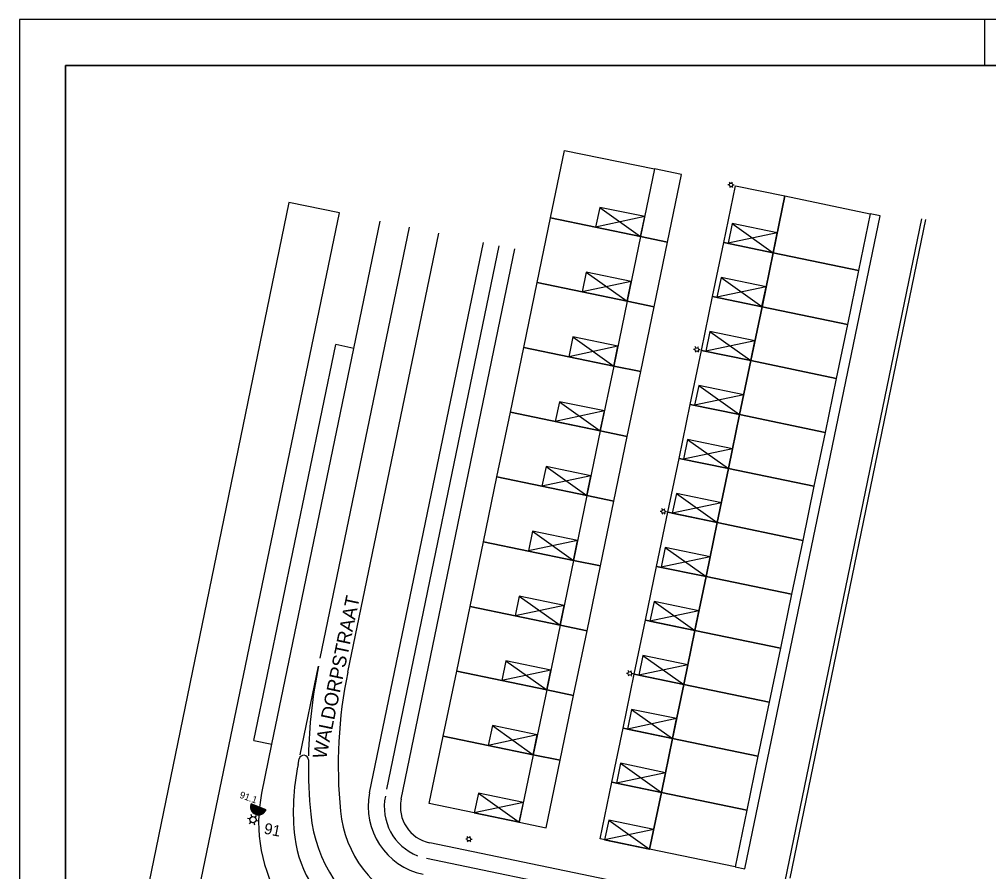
# Model space of a CAD drawing. Extents: x 81065 to 81486, y 452384 to 452681.
# Drawn here: x 81065.2 to 81170.8, y 452587.8 to 452680.5 of the extents above; entities that cross this region are included whole.
import ezdxf

# ---------------------------------------------------------------- set-up
doc = ezdxf.new("R2010")
doc.units = 0
for name, color, linetype in [('B-BH-AL-TOPOGRAFIE_STRAATNAAM-S', 7, 'Continuous'), ('B-BH-IE-MEUBILAIR_WEGMEUBILAIR_LICHTMAST-S', 7, 'Continuous'), ('B-BH-OG-TOPOGRAFIE_BEBOUWING-GV', 7, 'Continuous'), ('B-BH-OG-TOPOGRAFIE_BEBOUWING_PANDSCHEIDING-GV', 7, 'Continuous'), ('B-BH-VH-KANTOPSLUITING-GV', 7, 'Continuous'), ('B-WE-VW-MARKERING_LANGS_STREEP_13_010-G', 7, 'Continuous'), ('B-WE-VW-MARKERING_LANGS_STREEP_30270_010-G', 7, 'Continuous'), ('B-WE-VW-MARKERING_LANGS_STREEP_DOORGETROKKEN_010-G', 7, 'Continuous'), ('N-WE-VW-VRI_ARMATUUR-S', 7, 'Continuous'), ('N-WE-VW-VRI_ARMATUUR-T18', 7, 'Continuous'), ('N-WE-VW-VRI_MAST-S', 7, 'Continuous'), ('N-WE-VW-VRI_RICHTINGNUMMER-T25', 7, 'Continuous'), ('X-XX-AL-TEKENBLAD_KADER-G', 7, 'Continuous'), ('X-XX-AL-TEKENBLAD_KADER_AFSNIJMARKERING-G', 7, 'Continuous'), ('X-XX-AL-TEKENBLAD_KADER_VOUWMERK-G', 7, 'Continuous'), ('X-XX-AL-TEKENBLAD_VIEWPORT-G', 7, 'Continuous')]:
    doc.layers.add(name, color=color, linetype=linetype)

msp = doc.modelspace()

# ---------------------------------------------------------------- linework, layer by layer
at = {"layer": 'B-BH-IE-MEUBILAIR_WEGMEUBILAIR_LICHTMAST-S'}
for p, q in [((81142.5, 452662.52), (81142.35, 452662.52)), ((81142.6, 452662.7), (81142.52, 452662.83)), ((81142.8, 452662.7), (81142.87, 452662.83)), ((81142.9, 452662.52), (81143.05, 452662.52)), ((81142.6, 452662.35), (81142.52, 452662.22)), ((81142.8, 452662.35), (81142.87, 452662.22)), ((81138.78, 452644.6), (81138.63, 452644.6)), ((81138.88, 452644.78), (81138.81, 452644.91)), ((81139.08, 452644.78), (81139.16, 452644.91)), ((81139.18, 452644.6), (81139.33, 452644.6)), ((81138.88, 452644.43), (81138.81, 452644.3)), ((81139.08, 452644.43), (81139.16, 452644.3)), ((81135.13, 452626.98), (81134.98, 452626.98)), ((81135.23, 452627.15), (81135.16, 452627.28)), ((81135.23, 452626.8), (81135.16, 452626.67)), ((81135.43, 452627.15), (81135.51, 452627.28)), ((81135.43, 452626.8), (81135.51, 452626.67)), ((81135.53, 452626.98), (81135.68, 452626.98)), ((81131.58, 452609.52), (81131.51, 452609.65)), ((81131.78, 452609.52), (81131.86, 452609.65)), ((81131.48, 452609.35), (81131.33, 452609.35)), ((81131.58, 452609.18), (81131.51, 452609.05)), ((81131.78, 452609.18), (81131.86, 452609.05)), ((81131.88, 452609.35), (81132.03, 452609.35)), ((81113.96, 452591.31), (81113.81, 452591.31)), ((81114.06, 452591.48), (81113.98, 452591.61)), ((81114.06, 452591.14), (81113.98, 452591.01)), ((81114.26, 452591.48), (81114.33, 452591.61)), ((81114.26, 452591.14), (81114.33, 452591.01)), ((81114.36, 452591.31), (81114.51, 452591.31))]:
    msp.add_line(p, q, dxfattribs=at)
for centre in [(81142.7, 452662.52), (81138.98, 452644.6), (81135.33, 452626.98), (81131.68, 452609.35), (81114.16, 452591.31)]:
    msp.add_circle(centre, 0.2, dxfattribs=at)
at = {"layer": 'B-BH-OG-TOPOGRAFIE_BEBOUWING-GV'}
for points in [[(81132.85, 452656.9), (81123.06, 452658.93), (81124.58, 452666.27), (81134.37, 452664.25)], [(81148.57, 452661.31), (81157.87, 452659.38), (81156.6, 452653.21), (81147.29, 452655.14)], [(81132.85, 452656.9), (81131.39, 452649.85), (81121.6, 452651.88), (81123.06, 452658.93)], [(81147.29, 452655.14), (81156.6, 452653.21), (81155.38, 452647.33), (81146.08, 452649.26)], [(81131.39, 452649.85), (81129.93, 452642.8), (81120.14, 452644.83), (81121.6, 452651.88)], [(81146.08, 452649.26), (81155.38, 452647.33), (81154.16, 452641.46), (81144.86, 452643.39)], [(81129.93, 452642.8), (81128.47, 452635.75), (81118.68, 452637.78), (81120.14, 452644.83)], [(81144.86, 452643.39), (81154.16, 452641.46), (81152.94, 452635.58), (81143.64, 452637.51)], [(81128.47, 452635.75), (81127.01, 452628.7), (81117.22, 452630.73), (81118.68, 452637.78)], [(81143.64, 452637.51), (81152.94, 452635.58), (81151.73, 452629.71), (81142.42, 452631.64)], [(81127.01, 452628.7), (81125.55, 452621.65), (81115.76, 452623.68), (81117.22, 452630.73)], [(81142.42, 452631.64), (81151.73, 452629.71), (81150.51, 452623.83), (81141.21, 452625.76)], [(81141.21, 452625.76), (81150.51, 452623.83), (81149.29, 452617.96), (81139.99, 452619.88)], [(81125.55, 452621.65), (81124.09, 452614.6), (81114.3, 452616.63), (81115.76, 452623.68)], [(81139.99, 452619.88), (81149.29, 452617.96), (81148.08, 452612.08), (81138.77, 452614.01)], [(81124.09, 452614.6), (81122.63, 452607.55), (81112.84, 452609.58), (81114.3, 452616.63)], [(81138.77, 452614.01), (81148.08, 452612.08), (81146.86, 452606.21), (81137.56, 452608.13)], [(81122.63, 452607.55), (81121.17, 452600.5), (81111.37, 452602.53), (81112.84, 452609.58)], [(81137.56, 452608.13), (81146.86, 452606.21), (81145.64, 452600.33), (81136.34, 452602.26)], [(81121.17, 452600.5), (81119.65, 452593.16), (81109.85, 452595.18), (81111.37, 452602.53)], [(81136.34, 452602.26), (81145.64, 452600.33), (81144.42, 452594.46), (81135.12, 452596.38)], [(81135.12, 452596.38), (81144.42, 452594.46), (81143.15, 452588.29), (81133.84, 452590.21)]]:
    msp.add_lwpolyline(points, close=True, dxfattribs=at)
at = {"layer": 'B-BH-OG-TOPOGRAFIE_BEBOUWING_PANDSCHEIDING-GV'}
for p, q in [((81128.4, 452660.07), (81132.85, 452656.9)), ((81133.3, 452659.06), (81127.95, 452657.92)), ((81142.84, 452658.31), (81147.29, 452655.14)), ((81147.73, 452657.3), (81142.39, 452656.16)), ((81126.94, 452653.02), (81131.39, 452649.85)), ((81131.84, 452652.01), (81126.49, 452650.87)), ((81141.62, 452652.43), (81146.07, 452649.27)), ((81146.52, 452651.42), (81141.17, 452650.28)), ((81140.4, 452646.56), (81144.85, 452643.39)), ((81125.48, 452645.97), (81129.93, 452642.8)), ((81145.3, 452645.55), (81139.96, 452644.41)), ((81130.38, 452644.96), (81125.03, 452643.82)), ((81139.19, 452640.68), (81143.64, 452637.52)), ((81144.08, 452639.67), (81138.74, 452638.53)), ((81124.02, 452638.92), (81128.47, 452635.75)), ((81128.92, 452637.91), (81123.57, 452636.77)), ((81137.97, 452634.81), (81142.42, 452631.64)), ((81142.86, 452633.79), (81137.52, 452632.65)), ((81122.56, 452631.87), (81127.01, 452628.7)), ((81127.45, 452630.86), (81122.11, 452629.72)), ((81136.75, 452628.93), (81141.2, 452625.77)), ((81141.65, 452627.92), (81136.31, 452626.78)), ((81121.1, 452624.82), (81125.55, 452621.65)), ((81125.99, 452623.81), (81120.65, 452622.67)), ((81135.53, 452623.06), (81139.98, 452619.89)), ((81140.43, 452622.04), (81135.09, 452620.9)), ((81119.64, 452617.77), (81124.09, 452614.6)), ((81134.32, 452617.18), (81138.77, 452614.01)), ((81124.53, 452616.75), (81119.19, 452615.61)), ((81139.21, 452616.17), (81133.87, 452615.03)), ((81118.18, 452610.72), (81122.63, 452607.55)), ((81133.1, 452611.31), (81137.55, 452608.14)), ((81123.07, 452609.7), (81117.73, 452608.56)), ((81138, 452610.29), (81132.65, 452609.15)), ((81131.88, 452605.43), (81136.33, 452602.26)), ((81136.78, 452604.42), (81131.44, 452603.28)), ((81116.72, 452603.67), (81121.17, 452600.5)), ((81121.61, 452602.65), (81116.27, 452601.51)), ((81130.67, 452599.56), (81135.12, 452596.39)), ((81135.56, 452598.54), (81130.22, 452597.4)), ((81115.2, 452596.32), (81119.65, 452593.16)), ((81120.09, 452595.31), (81114.75, 452594.17)), ((81129.39, 452593.39), (81133.84, 452590.22)), ((81134.28, 452592.37), (81128.94, 452591.23))]:
    msp.add_line(p, q, dxfattribs=at)
for points in [[(81127.95, 452657.92), (81132.85, 452656.9), (81133.3, 452659.06), (81128.4, 452660.07)], [(81142.39, 452656.16), (81147.29, 452655.14), (81147.73, 452657.3), (81142.84, 452658.31)], [(81126.49, 452650.87), (81131.39, 452649.85), (81131.84, 452652.01), (81126.94, 452653.02)], [(81141.17, 452650.28), (81146.07, 452649.27), (81146.52, 452651.42), (81141.62, 452652.43)], [(81139.96, 452644.41), (81144.85, 452643.39), (81145.3, 452645.55), (81140.4, 452646.56)], [(81125.03, 452643.82), (81129.93, 452642.8), (81130.38, 452644.96), (81125.48, 452645.97)], [(81138.74, 452638.53), (81143.64, 452637.52), (81144.08, 452639.67), (81139.19, 452640.68)], [(81123.57, 452636.77), (81128.47, 452635.75), (81128.92, 452637.91), (81124.02, 452638.92)], [(81137.52, 452632.65), (81142.42, 452631.64), (81142.86, 452633.79), (81137.97, 452634.81)], [(81122.11, 452629.72), (81127.01, 452628.7), (81127.45, 452630.86), (81122.56, 452631.87)], [(81136.31, 452626.78), (81141.2, 452625.77), (81141.65, 452627.92), (81136.75, 452628.93)], [(81120.65, 452622.67), (81125.55, 452621.65), (81125.99, 452623.81), (81121.1, 452624.82)], [(81135.09, 452620.9), (81139.98, 452619.89), (81140.43, 452622.04), (81135.53, 452623.06)], [(81119.19, 452615.61), (81124.09, 452614.6), (81124.53, 452616.75), (81119.64, 452617.77)], [(81133.87, 452615.03), (81138.77, 452614.01), (81139.21, 452616.17), (81134.32, 452617.18)], [(81117.73, 452608.56), (81122.63, 452607.55), (81123.07, 452609.7), (81118.18, 452610.72)], [(81132.65, 452609.15), (81137.55, 452608.14), (81138, 452610.29), (81133.1, 452611.31)], [(81131.44, 452603.28), (81136.33, 452602.26), (81136.78, 452604.42), (81131.88, 452605.43)], [(81116.27, 452601.51), (81121.17, 452600.5), (81121.61, 452602.65), (81116.72, 452603.67)], [(81130.22, 452597.4), (81135.12, 452596.39), (81135.56, 452598.54), (81130.67, 452599.56)], [(81114.75, 452594.17), (81119.65, 452593.16), (81120.09, 452595.31), (81115.2, 452596.32)], [(81128.94, 452591.23), (81133.84, 452590.22), (81134.28, 452592.37), (81129.39, 452593.39)]]:
    msp.add_lwpolyline(points, close=True, dxfattribs=at)
at = {"layer": 'B-BH-VH-KANTOPSLUITING-GV'}
for p, q in [((81158.95, 452659.16), (81157.87, 452659.38)), ((81101.63, 452644.72), (81104.5, 452658.57)), ((81144.22, 452588.06), (81158.95, 452659.16)), ((81148.61, 452586.73), (81163.49, 452658.84)), ((81149.13, 452587.07), (81163.92, 452658.74)), ((81100.97, 452609.49), (81110.87, 452657.26)), ((81103.35, 452596.34), (81115.75, 452656.26)), ((81106.78, 452595.64), (81119.17, 452655.55)), ((81090.74, 452602.05), (81099.67, 452645.13)), ((81092.7, 452601.64), (81101.63, 452644.72)), ((81101.63, 452644.72), (81099.67, 452645.13)), ((81090.74, 452602.05), (81092.7, 452601.64)), ((81091.6, 452596.31), (81092.7, 452601.64)), ((81191.05, 452574.1), (81109.89, 452590.91)), ((81143.15, 452588.29), (81144.22, 452588.06))]:
    msp.add_line(p, q, dxfattribs=at)
for points in [[(81137.31, 452663.64), (81134.37, 452664.25), (81132.85, 452656.9), (81135.79, 452656.29)], [(81147.29, 452655.14), (81141.91, 452656.25), (81143.18, 452662.42), (81148.57, 452661.31)], [(81135.79, 452656.29), (81132.85, 452656.9), (81131.39, 452649.85), (81134.33, 452649.24)], [(81146.08, 452649.26), (81140.69, 452650.38), (81141.91, 452656.25), (81147.29, 452655.14)], [(81134.33, 452649.24), (81131.39, 452649.85), (81129.93, 452642.8), (81132.87, 452642.19)], [(81144.86, 452643.39), (81139.47, 452644.5), (81140.69, 452650.38), (81146.08, 452649.26)], [(81143.64, 452637.51), (81138.26, 452638.63), (81139.47, 452644.5), (81144.86, 452643.39)], [(81132.87, 452642.19), (81129.93, 452642.8), (81128.47, 452635.75), (81131.41, 452635.14)], [(81142.42, 452631.64), (81137.04, 452632.75), (81138.26, 452638.63), (81143.64, 452637.51)], [(81131.41, 452635.14), (81128.47, 452635.75), (81127.01, 452628.7), (81129.95, 452628.09)], [(81141.21, 452625.76), (81135.82, 452626.88), (81137.04, 452632.75), (81142.42, 452631.64)], [(81129.95, 452628.09), (81127.01, 452628.7), (81125.55, 452621.65), (81128.49, 452621.04)], [(81139.99, 452619.88), (81134.6, 452621), (81135.82, 452626.88), (81141.21, 452625.76)], [(81128.49, 452621.04), (81125.55, 452621.65), (81124.09, 452614.6), (81127.03, 452613.99)], [(81138.77, 452614.01), (81133.39, 452615.13), (81134.6, 452621), (81139.99, 452619.88)], [(81137.56, 452608.13), (81132.17, 452609.25), (81133.39, 452615.13), (81138.77, 452614.01)], [(81127.03, 452613.99), (81124.09, 452614.6), (81122.63, 452607.55), (81125.56, 452606.94)], [(81136.34, 452602.26), (81130.95, 452603.37), (81132.17, 452609.25), (81137.56, 452608.13)], [(81125.56, 452606.94), (81122.63, 452607.55), (81121.17, 452600.5), (81124.1, 452599.89)], [(81135.12, 452596.38), (81129.74, 452597.5), (81130.95, 452603.37), (81136.34, 452602.26)], [(81124.1, 452599.89), (81121.17, 452600.5), (81119.65, 452593.16), (81122.58, 452592.55)], [(81133.84, 452590.21), (81128.46, 452591.33), (81129.74, 452597.5), (81135.12, 452596.38)]]:
    msp.add_lwpolyline(points, close=True, dxfattribs=at)
for points in [[(81100.07, 452659.48), (81094.54, 452660.61), (81078.26, 452581.39)], [(81078.26, 452581.39), (81083.63, 452580.28), (81100.07, 452659.48)]]:
    msp.add_lwpolyline(points, dxfattribs=at)
for centre, radius, start, end in [((81149.93, 452599.34), 50, 168.2893, 185.7359), ((81107.26, 452593.07), 16, 168.2893, 258.3266), ((81110.7, 452594.83), 7.5, 168.3133, 258.2967), ((81110.7, 452594.83), 4, 168.3133, 258.2967), ((81112.61, 452595.59), 12.5, 185.7359, 248.4832)]:
    msp.add_arc(centre, radius, start, end, dxfattribs=at)
at = {"layer": 'B-WE-VW-MARKERING_LANGS_STREEP_13_010-G'}
msp.add_line((81097.96, 452611.02), (81107.68, 452657.91), dxfattribs=at)
at = {"layer": 'B-WE-VW-MARKERING_LANGS_STREEP_30270_010-G'}
for p, q in [((81105.22, 452596.73), (81117.46, 452655.9)), ((81191.19, 452572.28), (81109.53, 452589.2))]:
    msp.add_line(p, q, dxfattribs=at)
msp.add_arc((81110.7, 452594.83), 5.75, 168.3133, 248.3375, dxfattribs=at)
at = {"layer": 'B-WE-VW-MARKERING_LANGS_STREEP_DOORGETROKKEN_010-G'}
for p, q in [((81095.78, 452600.5), (81097.78, 452610.15)), ((81095.57, 452599.44), (81095.69, 452600.04))]:
    msp.add_line(p, q, dxfattribs=at)
for centre, radius, start, end in [((81149.93, 452599.34), 53.25, 168.2893, 178.9046), ((81096.18, 452599.94), 0.5, 359.3587, 168.2893), ((81120.04, 452594.37), 25, 168.2893, 186.5509), ((81149.93, 452599.34), 53.25, 179.3587, 185.7359), ((81112.61, 452595.59), 15.75, 185.7359, 241.1723), ((81107.13, 452592.89), 12, 186.5509, 241.5189)]:
    msp.add_arc(centre, radius, start, end, dxfattribs=at)
at = {"layer": 'N-WE-VW-VRI_ARMATUUR-S'}
for p, q in [((81091.92, 452594.26), (81090.38, 452594.87)), ((81091.98, 452594.33), (81090.39, 452594.97)), ((81091.96, 452594.31), (81090.39, 452594.94)), ((81091.94, 452594.28), (81090.39, 452594.91)), ((81092, 452594.36), (81090.4, 452595)), ((81092.01, 452594.38), (81090.41, 452595.03)), ((81092.04, 452594.44), (81090.42, 452595.08)), ((81092.03, 452594.41), (81090.42, 452595.06)), ((81092.05, 452594.46), (81090.43, 452595.11)), ((81092.07, 452594.49), (81090.45, 452595.14)), ((81091.9, 452594.23), (81090.38, 452594.84)), ((81091.88, 452594.21), (81090.38, 452594.81)), ((81091.86, 452594.19), (81090.38, 452594.78)), ((81091.83, 452594.17), (81090.39, 452594.75)), ((81091.81, 452594.14), (81090.39, 452594.71)), ((81091.78, 452594.12), (81090.39, 452594.68)), ((81091.75, 452594.1), (81090.4, 452594.64)), ((81091.72, 452594.08), (81090.41, 452594.61)), ((81091.69, 452594.06), (81090.42, 452594.57)), ((81091.66, 452594.04), (81090.43, 452594.54)), ((81091.62, 452594.02), (81090.44, 452594.5)), ((81091.58, 452594.01), (81090.46, 452594.46)), ((81091.54, 452593.99), (81090.48, 452594.42)), ((81091.49, 452593.98), (81090.5, 452594.37)), ((81091.45, 452593.97), (81090.53, 452594.33)), ((81091.39, 452593.95), (81090.56, 452594.29)), ((81091.33, 452593.95), (81090.6, 452594.24)), ((81091.26, 452593.94), (81090.65, 452594.18)), ((81091.16, 452593.95), (81090.72, 452594.12)), ((81090.99, 452593.99), (81090.87, 452594.03))]:
    msp.add_line(p, q, dxfattribs=at)
msp.add_arc((81091.26, 452594.82), 0.873, 158.1078, 338.1078, dxfattribs=at)
at = {"layer": 'N-WE-VW-VRI_MAST-S'}
for p, q in [((81090.53, 452593.75), (81090.45, 452594)), ((81090.87, 452593.68), (81091.04, 452593.87)), ((81090.31, 452593.5), (81090.06, 452593.55)), ((81090.41, 452593.18), (81090.24, 452592.99)), ((81090.75, 452593.11), (81090.83, 452592.87)), ((81090.97, 452593.36), (81091.22, 452593.31))]:
    msp.add_line(p, q, dxfattribs=at)
msp.add_circle((81090.64, 452593.43), 0.34, dxfattribs=at)
at = {"layer": 'X-XX-AL-TEKENBLAD_KADER-G'}
msp.add_lwpolyline([(81480.71, 452388.53), (81070.22, 452388.53), (81070.22, 452675.53), (81480.71, 452675.53)], close=True, dxfattribs=at)
at = {"layer": 'X-XX-AL-TEKENBLAD_KADER_AFSNIJMARKERING-G'}
msp.add_lwpolyline([(81485.71, 452680.53), (81065.21, 452680.53), (81065.21, 452383.53), (81485.71, 452383.53)], close=True, dxfattribs=at)
at = {"layer": 'X-XX-AL-TEKENBLAD_KADER_VOUWMERK-G'}
msp.add_line((81170.34, 452675.53), (81170.34, 452680.53), dxfattribs=at)
at = {"layer": 'X-XX-AL-TEKENBLAD_VIEWPORT-G'}
msp.add_lwpolyline([(81070.22, 452388.53), (81480.71, 452388.53), (81480.71, 452675.53), (81070.22, 452675.53)], close=True, dxfattribs=at)

# ---------------------------------------------------------------- texts
at = {"layer": 'B-BH-AL-TOPOGRAFIE_STRAATNAAM-S'}
msp.add_text('WALDORPSTRAAT', height=1.5, rotation=78.2165, dxfattribs=at).set_placement((81098.6, 452599.95))
at = {"layer": 'N-WE-VW-VRI_ARMATUUR-T18'}
msp.add_text('91.1', height=0.75, rotation=340.1468, dxfattribs=at).set_placement((81089.12, 452595.83))
at = {"layer": 'N-WE-VW-VRI_RICHTINGNUMMER-T25'}
msp.add_text('91', height=1.2, rotation=348.3917, dxfattribs=at).set_placement((81091.78, 452591.92))

doc.saveas('drawing.dxf')
